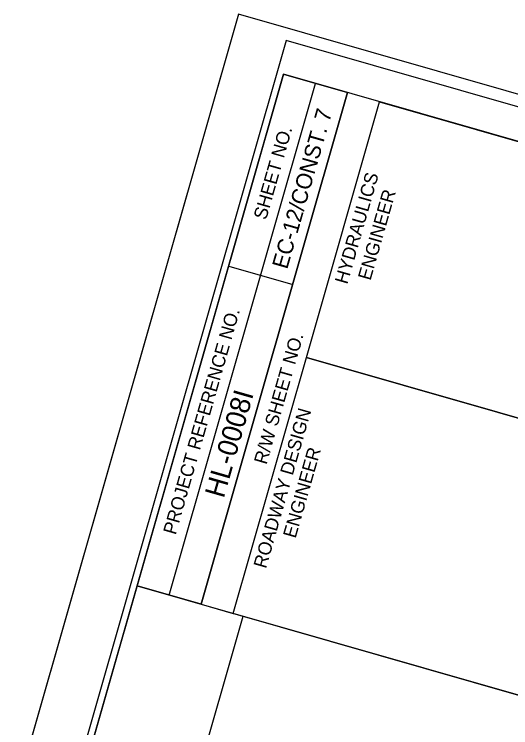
# Model space of a CAD drawing. Extents: x 2096976 to 2098492, y 681809 to 689636.
# Drawn here: x 2097354.7 to 2097541.4, y 689367.6 to 689635.8 of the extents above; entities that cross this region are included whole.
import ezdxf

# ---------------------------------------------------------------- set-up
doc = ezdxf.new("R2010")
doc.units = 0
for name, color, linetype in [('Scratch_Level_6', 7, 'Continuous'), ('Sheet Cutting Line CELL', 7, 'Continuous'), ('Sheet Data Field CELL', 7, 'Continuous'), ('Sheet Plan CELL', 7, 'Continuous'), ('Sheet Plot Border Inside CELL', 7, 'Continuous'), ('Sheet Plot Border Outside CELL', 7, 'Continuous')]:
    doc.layers.add(name, color=color, linetype=linetype)

msp = doc.modelspace()

# ---------------------------------------------------------------- linework, layer by layer
at = {"layer": 'Scratch_Level_6'}
msp.add_lwpolyline([(2098102.1, 688055.1), (2097347.73, 688084.03), (2097057.83, 688167.01), (2097360.53, 689224.43), (2097385.77, 689217.21), (2097440.82, 689409.53), (2097570.41, 689372.44), (2097625.46, 689564.76), (2098465.42, 689324.31)], close=True, dxfattribs=at)
at = {"layer": 'Sheet Cutting Line CELL'}
msp.add_line((2097439.02, 689635.81), (2096975.72, 688017.32), dxfattribs=at)
at = {"layer": 'Sheet Plan CELL'}
for p, q in [((2097412.96, 689417.49), (2097468.03, 689609.81)), ((2097425.02, 689414.05), (2097480.04, 689606.37)), ((2097425.02, 689414.05), (2097480.04, 689606.37)), ((2097435.38, 689541.12), (2097459.42, 689534.29)), ((2097464.56, 689506.8), (2097572.68, 689475.86)), ((2097425.02, 689414.05), (2097437.02, 689410.61))]:
    msp.add_line(p, q, dxfattribs=at)
for points in [[(2097455.97, 689613.3), (2097043.16, 688171.19), (2098052.61, 687882.22), (2098465.42, 689324.31)], [(2097400.9, 689420.95), (2097455.97, 689613.3), (2097480.04, 689606.37), (2097425.02, 689414.05)], [(2097464.56, 689506.8), (2097492.06, 689602.93), (2097600.23, 689571.98), (2097572.73, 689475.84)], [(2098052.61, 687882.22), (2097043.17, 688171.15), (2097400.9, 689420.95), (2097545.17, 689379.67), (2097600.23, 689571.98), (2098465.42, 689324.31)], [(2097437.02, 689410.61), (2097464.56, 689506.8), (2097572.73, 689475.84), (2097545.17, 689379.67)]]:
    msp.add_lwpolyline(points, close=True, dxfattribs=at)
at = {"layer": 'Sheet Plot Border Inside CELL'}
msp.add_lwpolyline([(2098012.79, 687733.97), (2098471.26, 689335.63), (2097457.01, 689625.98), (2096998.53, 688024.31)], close=True, dxfattribs=at)
at = {"layer": 'Sheet Plot Border Outside CELL'}
msp.add_lwpolyline([(2098028.44, 687715.97), (2098491.74, 689334.46), (2097439.02, 689635.81), (2096975.72, 688017.32)], close=True, dxfattribs=at)

# ---------------------------------------------------------------- texts
at = {"layer": 'Sheet Data Field CELL'}
for s, height, p in [('EC-12/CONST. 7', 6, (2097457.32, 689539.7)), ('HL-0008I', 7.5, (2097433.47, 689453.61))]:
    msp.add_text(s, height=height, rotation=74.0259, dxfattribs=at).set_placement(p)
at = {"layer": 'Sheet Plan CELL'}
for s, height, p in [('SHEET NO.', 5, (2097449.4, 689558.27)), ('HYDRAULICS', 5, (2097479.93, 689534.08)), ('ENGINEER', 5, (2097488.63, 689535.51)), ('PROJECT REFERENCE NO.', 5.0001, (2097415.4, 689439.9)), ('R/W SHEET NO.', 5.0001, (2097449.54, 689466.32)), ('ROADWAY DESIGN', 5.0001, (2097449.37, 689427.23)), ('ENGINEER', 5, (2097460.47, 689438.6))]:
    msp.add_text(s, height=height, rotation=74.0259, dxfattribs=at).set_placement(p)

doc.saveas('drawing.dxf')
